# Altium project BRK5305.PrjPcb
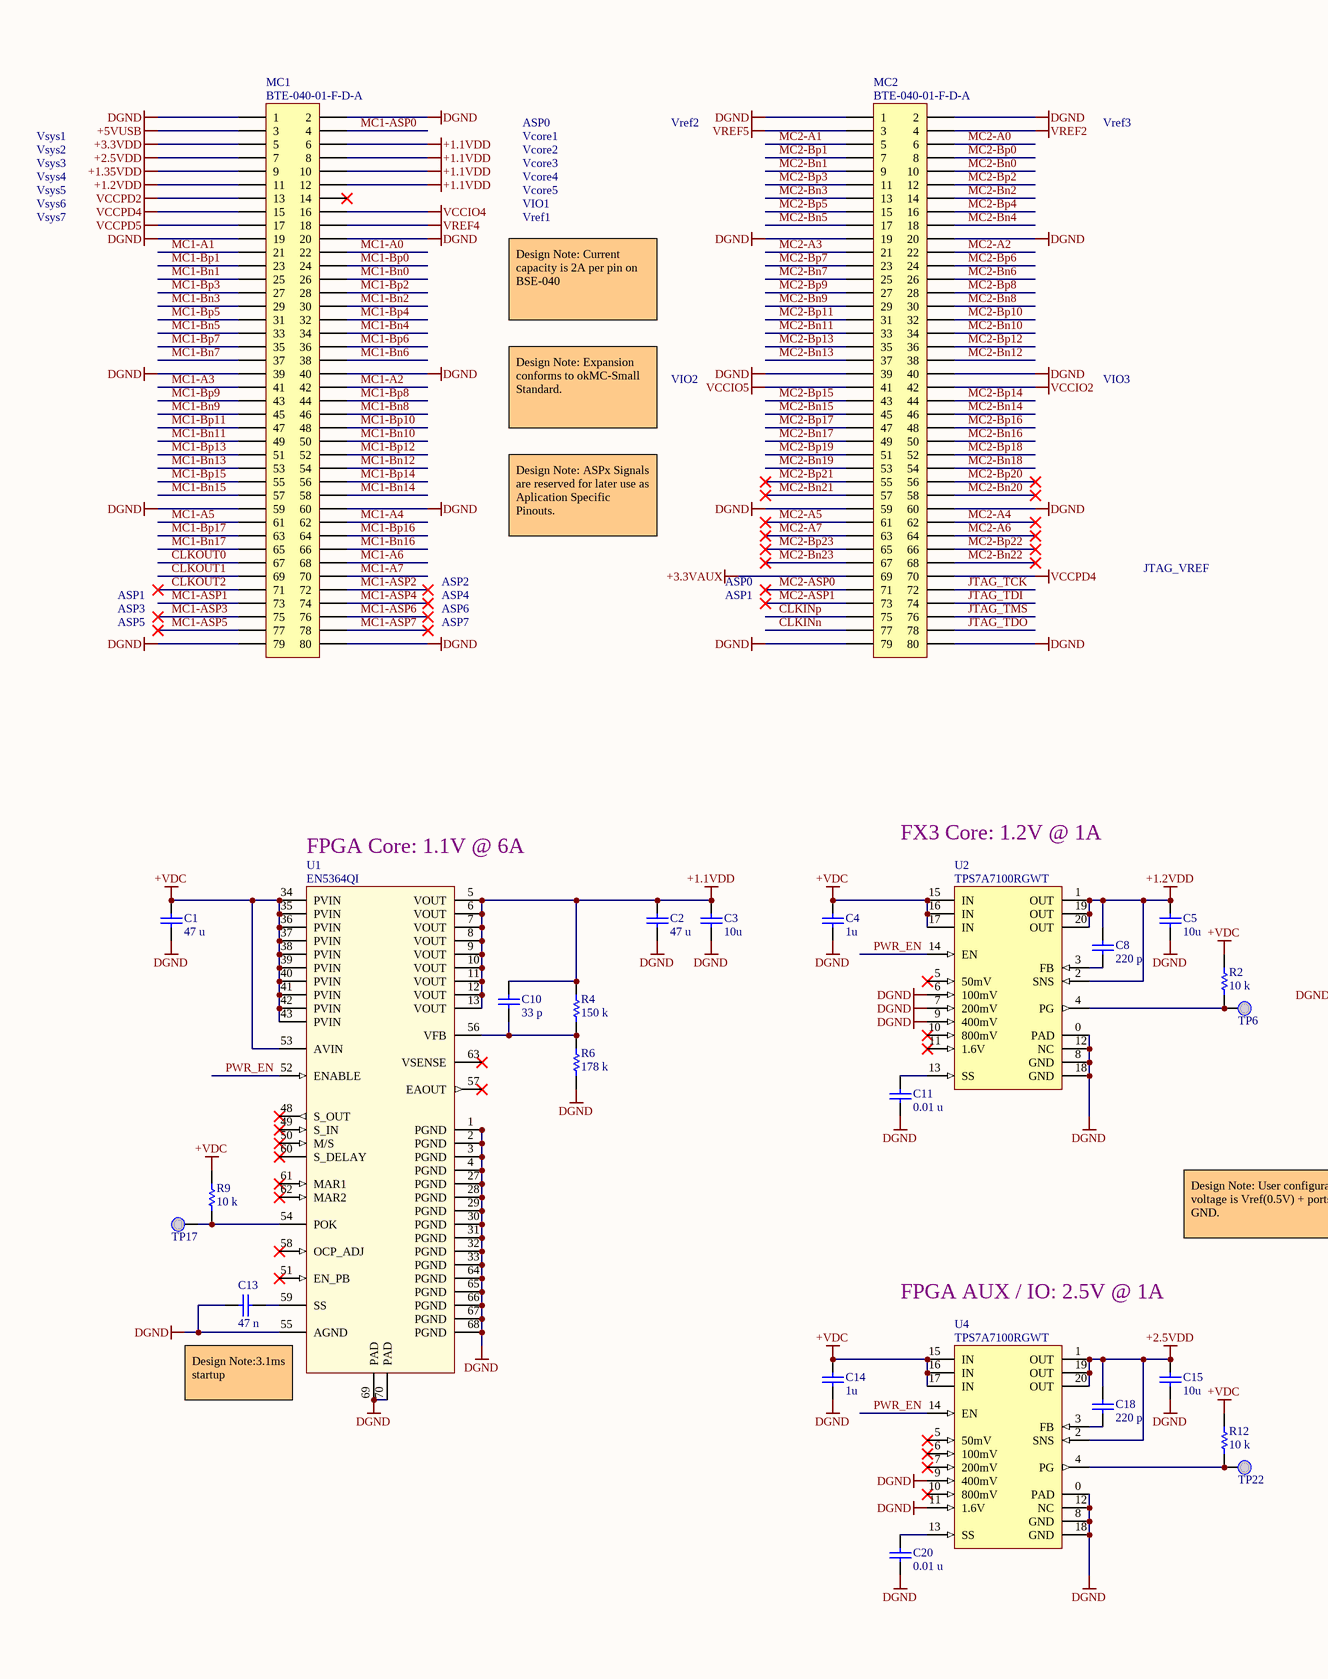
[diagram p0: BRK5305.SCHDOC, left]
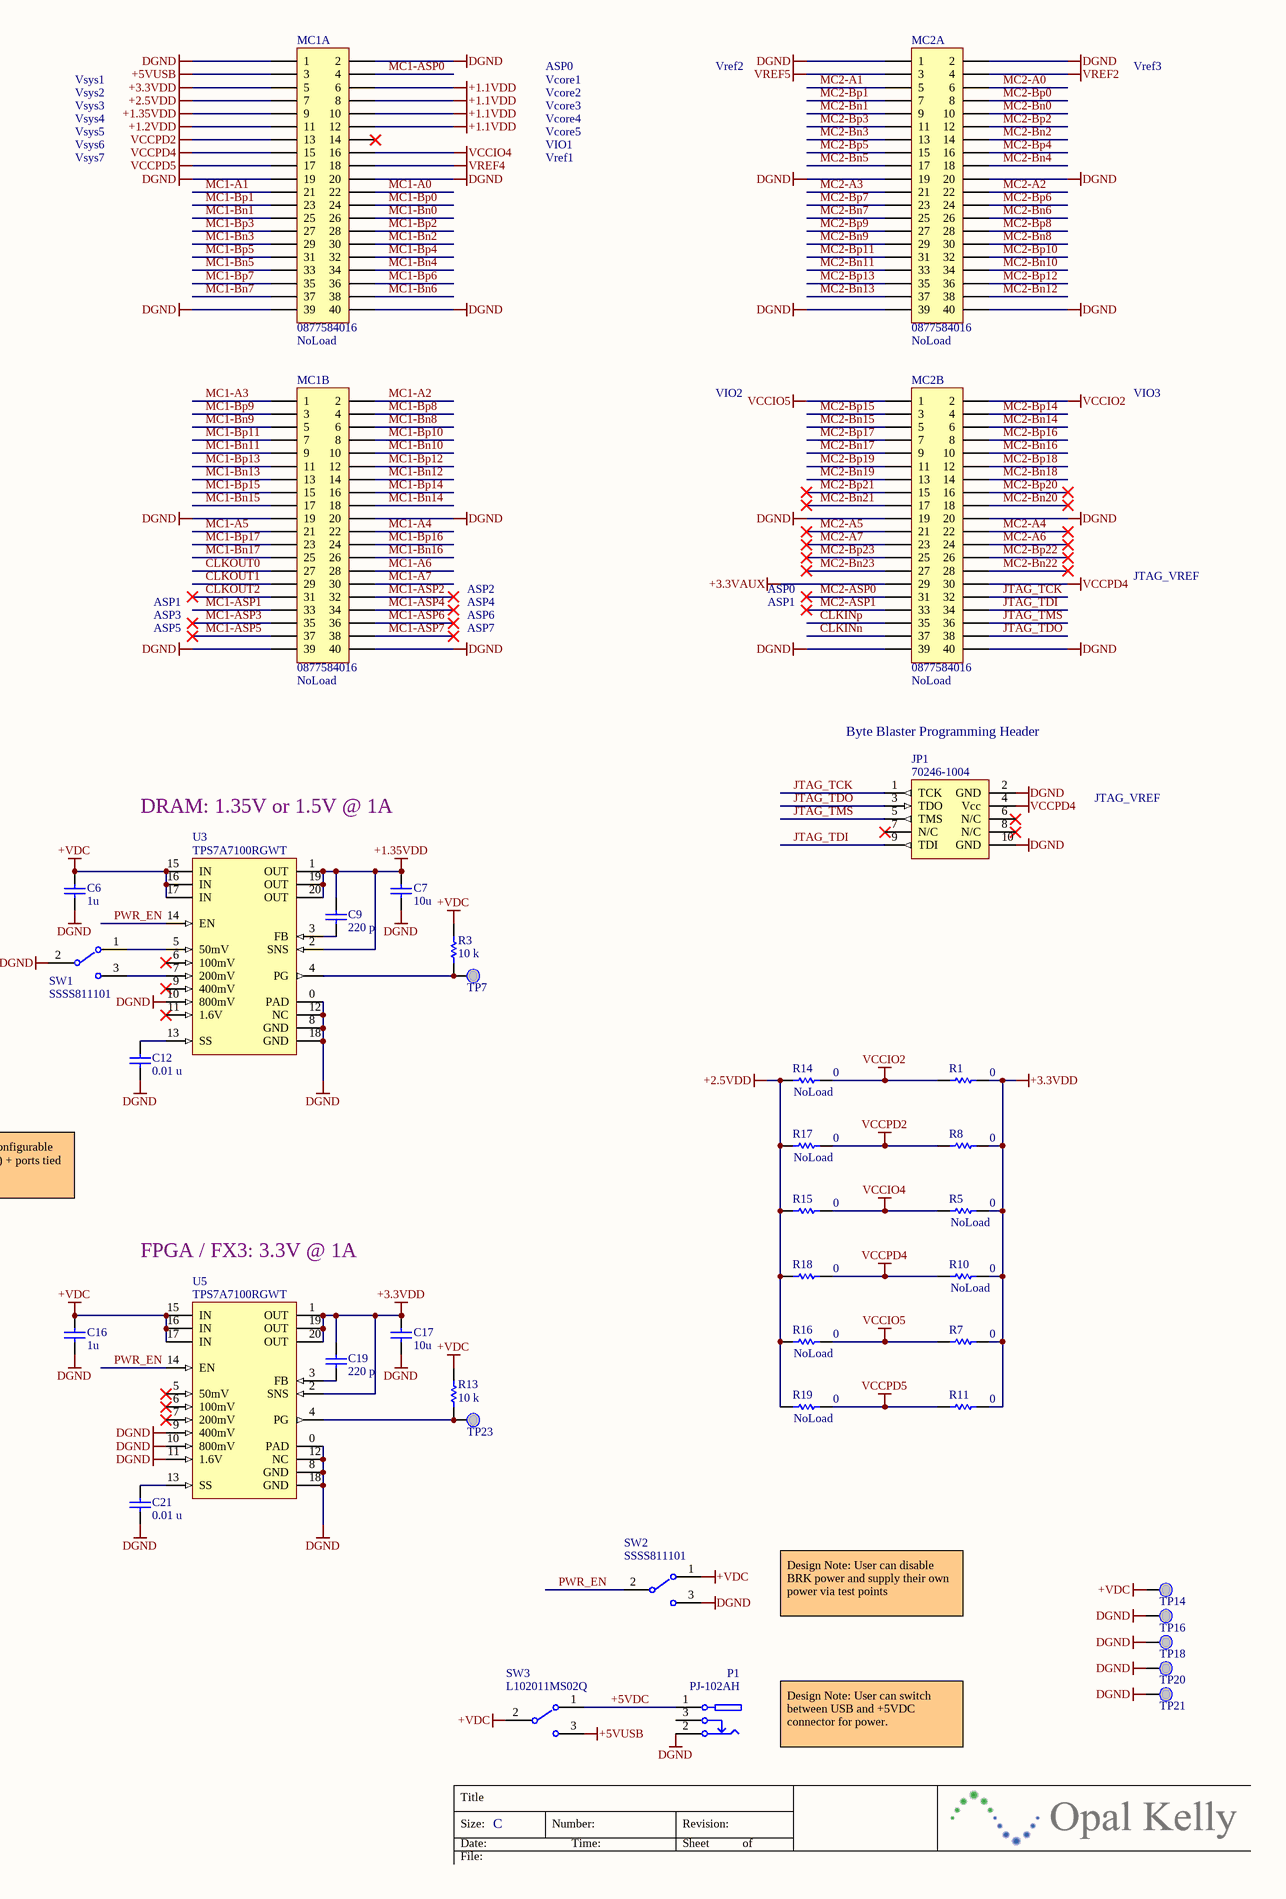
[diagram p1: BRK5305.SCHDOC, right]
1 sheet, 66 parts. Net scope: global (net labels, ports and power ports of the same name join across sheets).
Board file: BRK5305.PcbDoc

## Sheet BRK5305.SCHDOC: BRK5305 BreakOut Board
size C; Author: Casey Smith; Organization: Opal Kelly; Address1: 13500 SW 72nd Ave, STE 100; Address2: Portland, OR 97223; Address3: 217.391.3724; Address4: http://www.opalkelly.com; DocumentNumber: xxx; Revision: 1; SheetNumber: 1; SheetTotal: 1

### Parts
C1  value 47 u  [CAPC3216N]  (hidden comment: JMK316BJ476ML-T)
C2  value 47 u  [CAPC3216N]  (hidden comment: JMK316BJ476ML-T)
C3  value 10u  [CAPC2012N]  (hidden comment: LMK212BJ106KG-T)
C4  value 1u  [CAPC1005N]  (hidden comment: LMK105BJ105KV-F)
C5  value 10u  [CAPC2012N]  (hidden comment: LMK212BJ106KG-T)
C6  value 1u  [CAPC1005N]  (hidden comment: LMK105BJ105KV-F)
C7  value 10u  [CAPC2012N]  (hidden comment: LMK212BJ106KG-T)
C8  value 220 p  [CAPC1005N]  (hidden comment: C0402C221J5GACTU)
C9  value 220 p  [CAPC1005N]  (hidden comment: C0402C221J5GACTU)
C10  value 33 p  [CAPC1005N]  (hidden comment: C0402C330J5GACTU)
C11  value 0.01 u  [CAPC1005N]  (hidden comment: C0402C103K4RACTU)
C12  value 0.01 u  [CAPC1005N]  (hidden comment: C0402C103K4RACTU)
C13  value 47 n  [CAPC1005N]  (hidden comment: EMK105BJ473KV-F)
C14  value 1u  [CAPC1005N]  (hidden comment: LMK105BJ105KV-F)
C15  value 10u  [CAPC2012N]  (hidden comment: LMK212BJ106KG-T)
C16  value 1u  [CAPC1005N]  (hidden comment: LMK105BJ105KV-F)
C17  value 10u  [CAPC2012N]  (hidden comment: LMK212BJ106KG-T)
C18  value 220 p  [CAPC1005N]  (hidden comment: C0402C221J5GACTU)
C19  value 220 p  [CAPC1005N]  (hidden comment: C0402C221J5GACTU)
C20  value 0.01 u  [CAPC1005N]  (hidden comment: C0402C103K4RACTU)
C21  value 0.01 u  [CAPC1005N]  (hidden comment: C0402C103K4RACTU)
JP1  70246-1004  [HDR2X5-SHRD]
MC1  BTE-040-01-F-D-A  [BTE-040]
MC1A  0877584016  [HDR2X20-2MM]
MC1B  0877584016  [HDR2X20-2MM]
MC2  BTE-040-01-F-D-A  [BTE-040]
MC2A  0877584016  [HDR2X20-2MM]
MC2B  0877584016  [HDR2X20-2MM]
P1  PJ-102AH  [CUI-PJ102A]
R1  value 0  [RESC1005N]  (hidden comment: CRCW04020000Z0ED)
R2  value 10 k  [RESC1005N]  (hidden comment: CRCW040210K0JNED)
R3  value 10 k  [RESC1005N]  (hidden comment: CRCW040210K0JNED)
R4  value 150 k  [RESC1005N]  (hidden comment: CRCW0402150KFKED)
R5  value 0  [RESC1005N]  (hidden comment: CRCW04020000Z0ED)
R6  value 178 k  [RESC1005N]  (hidden comment: CRCW0402178KFKED)
R7  value 0  [RESC1005N]  (hidden comment: CRCW04020000Z0ED)
R8  value 0  [RESC1005N]  (hidden comment: CRCW04020000Z0ED)
R9  value 10 k  [RESC1005N]  (hidden comment: CRCW040210K0JNED)
R10  value 0  [RESC1005N]  (hidden comment: CRCW04020000Z0ED)
R11  value 0  [RESC1005N]  (hidden comment: CRCW04020000Z0ED)
R12  value 10 k  [RESC1005N]  (hidden comment: CRCW040210K0JNED)
R13  value 10 k  [RESC1005N]  (hidden comment: CRCW040210K0JNED)
R14  value 0  [RESC1005N]  (hidden comment: CRCW04020000Z0ED)
R15  value 0  [RESC1005N]  (hidden comment: CRCW04020000Z0ED)
R16  value 0  [RESC1005N]  (hidden comment: CRCW04020000Z0ED)
R17  value 0  [RESC1005N]  (hidden comment: CRCW04020000Z0ED)
R18  value 0  [RESC1005N]  (hidden comment: CRCW04020000Z0ED)
R19  value 0  [RESC1005N]  (hidden comment: CRCW04020000Z0ED)
SW1  SSSS811101  [SSSS811101]
SW2  SSSS811101  [SSSS811101]
SW3  L102011MS02Q  [L102011MS]
TP6  1.2V POK  [TP_SMALL]  (value not drawn)
TP7  1.35V/1.5V POK  [TP_SMALL]  (value not drawn)
TP14  +VDC  [TP_MED]  (value not drawn)
TP16  GND  [TP_MED]  (value not drawn)
TP17  1.1V POK  [TP_SMALL]  (value not drawn)
TP18  GND  [TP_MED]  (value not drawn)
TP20  GND  [TP_MED]  (value not drawn)
TP21  GND  [TP_MED]  (value not drawn)
TP22  2.5V POK  [TP_SMALL]  (value not drawn)
TP23  3.3V POK  [TP_SMALL]  (value not drawn)
U1  EN5364QI  [EN5364]
U2  TPS7A7100RGWT  [S-PVQN-N20]
U3  TPS7A7100RGWT  [S-PVQN-N20]
U4  TPS7A7100RGWT  [S-PVQN-N20]
U5  TPS7A7100RGWT  [S-PVQN-N20]

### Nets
+1.1VDD: C2.2 C3.2 C10.2 MC1.6 MC1.8 MC1.10 MC1.12 MC1A.6 MC1A.8 MC1A.10 MC1A.12 R4.2 U1.5(VOUT) U1.6(VOUT) U1.7(VOUT) U1.8(VOUT) U1.9(VOUT) U1.10(VOUT) U1.11(VOUT) U1.12(VOUT) U1.13(VOUT)
+1.2VDD: C5.2 C8.2 MC1.11 MC1A.11 U2.1(OUT) U2.2(SNS) U2.19(OUT) U2.20(OUT)
+1.35VDD: C7.2 C9.2 MC1.9 MC1A.9 U3.1(OUT) U3.2(SNS) U3.19(OUT) U3.20(OUT)
+2.5VDD: C15.2 C18.2 MC1.7 MC1A.7 R14.1 R15.1 R16.1 R17.1 R18.1 R19.1 U4.1(OUT) U4.2(SNS) U4.19(OUT) U4.20(OUT)
+3.3VAUX: MC2.69 MC2B.29
+3.3VDD: C17.2 C19.2 MC1.5 MC1A.5 R1.2 R5.2 R7.2 R8.2 R10.2 R11.2 U5.1(OUT) U5.2(SNS) U5.19(OUT) U5.20(OUT)
+5VUSB: MC1.3 MC1A.3 SW3.3
+VDC: C1.2 C4.2 C6.2 C14.2 C16.2 R2.2 R3.2 R9.2 R12.2 R13.2 SW2.1 SW3.2 TP14.1(PIN) U1.34(PVIN) U1.35(PVIN) U1.36(PVIN) U1.37(PVIN) U1.38(PVIN) U1.39(PVIN) U1.40(PVIN) U1.41(PVIN) U1.42(PVIN) U1.43(PVIN) U1.53(AVIN) U2.15(IN) U2.16(IN) U2.17(IN) U3.15(IN) U3.16(IN) U3.17(IN) U4.15(IN) U4.16(IN) U4.17(IN) U5.15(IN) U5.16(IN) U5.17(IN)
DGND: C1.1 C2.1 C3.1 C4.1 C5.1 C6.1 C7.1 C11.1 C12.1 C13.1 C14.1 C15.1 C16.1 C17.1 C20.1 C21.1 JP1.2(GND) JP1.10(GND) MC1.1 MC1.2 MC1.19 MC1.20 MC1.39 MC1.40 MC1.59 MC1.60 MC1.79 MC1.80 MC1A.1 MC1A.2 MC1A.19 MC1A.20 MC1A.39 MC1A.40 MC1B.19 MC1B.20 MC1B.39 MC1B.40 MC2.1 MC2.2 MC2.19 MC2.20 MC2.39 MC2.40 MC2.59 MC2.60 MC2.79 MC2.80 MC2A.1 MC2A.2 MC2A.19 MC2A.20 MC2A.39 MC2A.40 MC2B.19 MC2B.20 MC2B.39 MC2B.40 P1.2 R6.1 SW1.2 SW2.3 TP16.1(PIN) TP18.1(PIN) TP20.1(PIN) TP21.1(PIN) U1.1(PGND) U1.2(PGND) U1.3(PGND) U1.4(PGND) U1.27(PGND) U1.28(PGND) U1.29(PGND) U1.30(PGND) U1.31(PGND) U1.32(PGND) U1.33(PGND) U1.55(AGND) U1.64(PGND) U1.65(PGND) U1.66(PGND) U1.67(PGND) U1.68(PGND) U1.69(PAD) U1.70(PAD) U2.0(PAD) U2.6(100mV) U2.7(200mV) U2.8(GND) U2.9(400mV) U2.12(NC) U2.18(GND) U3.0(PAD) U3.8(GND) U3.10(800mV) U3.12(NC) U3.18(GND) U4.0(PAD) U4.8(GND) U4.9(400mV) U4.11(1.6V) U4.12(NC) U4.18(GND) U5.0(PAD) U5.8(GND) U5.9(400mV) U5.10(800mV) U5.11(1.6V) U5.12(NC) U5.18(GND)
VCCIO2: MC2.42 MC2B.2 R1.1 R14.2
VCCIO4: MC1.16 MC1A.16 R5.1 R15.2
VCCIO5: MC2.41 MC2B.1 R7.1 R16.2
VCCPD2: MC1.13 MC1A.13 R8.1 R17.2
VCCPD4: JP1.4(Vcc) MC1.15 MC1A.15 MC2.70 MC2B.30 R10.1 R18.2
VCCPD5: MC1.17 MC1A.17 R11.1 R19.2
VREF2: MC2.4 MC2A.4
VREF4: MC1.18 MC1A.18
VREF5: MC2.3 MC2A.3
+5VDC: P1.1 SW3.1
CLKINn: MC2.77 MC2B.37
CLKINp: MC2.75 MC2B.35
CLKOUT0: MC1.67 MC1B.27
CLKOUT1: MC1.69 MC1B.29
CLKOUT2: MC1.71 MC1B.31
JTAG_TCK: JP1.1(TCK) MC2.72 MC2B.32
JTAG_TDI: JP1.9(TDI) MC2.74 MC2B.34
JTAG_TDO: JP1.3(TDO) MC2.78 MC2B.38
JTAG_TMS: JP1.5(TMS) MC2.76 MC2B.36
MC1-A0: MC1.22 MC1A.22
MC1-A1: MC1.21 MC1A.21
MC1-A2: MC1.42 MC1B.2
MC1-A3: MC1.41 MC1B.1
MC1-A4: MC1.62 MC1B.22
MC1-A5: MC1.61 MC1B.21
MC1-A6: MC1.68 MC1B.28
MC1-A7: MC1.70 MC1B.30
MC1-ASP0: MC1.4 MC1A.4
MC1-ASP1: MC1.73 MC1B.33
MC1-ASP2: MC1.72 MC1B.32
MC1-ASP3: MC1.75 MC1B.35
MC1-ASP4: MC1.74 MC1B.34
MC1-ASP5: MC1.77 MC1B.37
MC1-ASP6: MC1.76 MC1B.36
MC1-ASP7: MC1.78 MC1B.38
MC1-Bn0: MC1.26 MC1A.26
MC1-Bn1: MC1.25 MC1A.25
MC1-Bn2: MC1.30 MC1A.30
MC1-Bn3: MC1.29 MC1A.29
MC1-Bn4: MC1.34 MC1A.34
MC1-Bn5: MC1.33 MC1A.33
MC1-Bn6: MC1.38 MC1A.38
MC1-Bn7: MC1.37 MC1A.37
MC1-Bn8: MC1.46 MC1B.6
MC1-Bn9: MC1.45 MC1B.5
MC1-Bn10: MC1.50 MC1B.10
MC1-Bn11: MC1.49 MC1B.9
MC1-Bn12: MC1.54 MC1B.14
MC1-Bn13: MC1.53 MC1B.13
MC1-Bn14: MC1.58 MC1B.18
MC1-Bn15: MC1.57 MC1B.17
MC1-Bn16: MC1.66 MC1B.26
MC1-Bn17: MC1.65 MC1B.25
MC1-Bp0: MC1.24 MC1A.24
MC1-Bp1: MC1.23 MC1A.23
MC1-Bp2: MC1.28 MC1A.28
MC1-Bp3: MC1.27 MC1A.27
MC1-Bp4: MC1.32 MC1A.32
MC1-Bp5: MC1.31 MC1A.31
MC1-Bp6: MC1.36 MC1A.36
MC1-Bp7: MC1.35 MC1A.35
MC1-Bp8: MC1.44 MC1B.4
MC1-Bp9: MC1.43 MC1B.3
MC1-Bp10: MC1.48 MC1B.8
MC1-Bp11: MC1.47 MC1B.7
MC1-Bp12: MC1.52 MC1B.12
MC1-Bp13: MC1.51 MC1B.11
MC1-Bp14: MC1.56 MC1B.16
MC1-Bp15: MC1.55 MC1B.15
MC1-Bp16: MC1.64 MC1B.24
MC1-Bp17: MC1.63 MC1B.23
MC2-A0: MC2.6 MC2A.6
MC2-A1: MC2.5 MC2A.5
MC2-A2: MC2.22 MC2A.22
MC2-A3: MC2.21 MC2A.21
MC2-A4: MC2.62 MC2B.22
MC2-A5: MC2.61 MC2B.21
MC2-A6: MC2.64 MC2B.24
MC2-A7: MC2.63 MC2B.23
MC2-ASP0: MC2.71 MC2B.31
MC2-ASP1: MC2.73 MC2B.33
MC2-Bn0: MC2.10 MC2A.10
MC2-Bn1: MC2.9 MC2A.9
MC2-Bn2: MC2.14 MC2A.14
MC2-Bn3: MC2.13 MC2A.13
MC2-Bn4: MC2.18 MC2A.18
MC2-Bn5: MC2.17 MC2A.17
MC2-Bn6: MC2.26 MC2A.26
MC2-Bn7: MC2.25 MC2A.25
MC2-Bn8: MC2.30 MC2A.30
MC2-Bn9: MC2.29 MC2A.29
MC2-Bn10: MC2.34 MC2A.34
MC2-Bn11: MC2.33 MC2A.33
MC2-Bn12: MC2.38 MC2A.38
MC2-Bn13: MC2.37 MC2A.37
MC2-Bn14: MC2.46 MC2B.6
MC2-Bn15: MC2.45 MC2B.5
MC2-Bn16: MC2.50 MC2B.10
MC2-Bn17: MC2.49 MC2B.9
MC2-Bn18: MC2.54 MC2B.14
MC2-Bn19: MC2.53 MC2B.13
MC2-Bn20: MC2.58 MC2B.18
MC2-Bn21: MC2.57 MC2B.17
MC2-Bn22: MC2.68 MC2B.28
MC2-Bn23: MC2.67 MC2B.27
MC2-Bp0: MC2.8 MC2A.8
MC2-Bp1: MC2.7 MC2A.7
MC2-Bp2: MC2.12 MC2A.12
MC2-Bp3: MC2.11 MC2A.11
MC2-Bp4: MC2.16 MC2A.16
MC2-Bp5: MC2.15 MC2A.15
MC2-Bp6: MC2.24 MC2A.24
MC2-Bp7: MC2.23 MC2A.23
MC2-Bp8: MC2.28 MC2A.28
MC2-Bp9: MC2.27 MC2A.27
MC2-Bp10: MC2.32 MC2A.32
MC2-Bp11: MC2.31 MC2A.31
MC2-Bp12: MC2.36 MC2A.36
MC2-Bp13: MC2.35 MC2A.35
MC2-Bp14: MC2.44 MC2B.4
MC2-Bp15: MC2.43 MC2B.3
MC2-Bp16: MC2.48 MC2B.8
MC2-Bp17: MC2.47 MC2B.7
MC2-Bp18: MC2.52 MC2B.12
MC2-Bp19: MC2.51 MC2B.11
MC2-Bp20: MC2.56 MC2B.16
MC2-Bp21: MC2.55 MC2B.15
MC2-Bp22: MC2.66 MC2B.26
MC2-Bp23: MC2.65 MC2B.25
PWR_EN: SW2.2 U1.52(ENABLE) U2.14(EN) U3.14(EN) U4.14(EN) U5.14(EN)
NetC8_1: C8.1 U2.3(FB)
NetC9_1: C9.1 U3.3(FB)
NetC10_1: C10.1 R4.1 R6.2 U1.56(VFB)
NetC11_2: C11.2 U2.13(SS)
NetC12_2: C12.2 U3.13(SS)
NetC13_2: C13.2 U1.59(SS)
NetC18_1: C18.1 U4.3(FB)
NetC19_1: C19.1 U5.3(FB)
NetC20_2: C20.2 U4.13(SS)
NetC21_2: C21.2 U5.13(SS)
NetR2_1: R2.1 TP6.1(PIN) U2.4(PG)
NetR3_1: R3.1 TP7.1(PIN) U3.4(PG)
NetR9_1: R9.1 TP17.1(PIN) U1.54(POK)
NetR12_1: R12.1 TP22.1(PIN) U4.4(PG)
NetR13_1: R13.1 TP23.1(PIN) U5.4(PG)
NetSW1_1: SW1.1 U3.5(50mV)
NetSW1_3: SW1.3 U3.7(200mV)

Not connected (* = marked no-connect by the designer): JP1 6(N/C)* 7(N/C)* 8(N/C)*; MC1 14*; MC1A 14*; P1 3; U1 48(S_OUT)* 49(S_IN)* 50(M/S)* 51(EN_PB)* 57(EAOUT)* 58(OCP_ADJ)* 60(S_DELAY)* 61(MAR1)* 62(MAR2)* 63(VSENSE)*; U2 5(50mV)* 10(800mV)* 11(1.6V)*; U3 6(100mV)* 9(400mV)* 11(1.6V)*; U4 5(50mV)* 6(100mV)* 7(200mV)* 10(800mV)*; U5 5(50mV)* 6(100mV)* 7(200mV)*

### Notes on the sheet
- Vsys1
- Vsys2
- ASP0
- Vcore2
- Vcore1
- Vref2
- Vref3
- Vsys3
- Vcore3
- Vsys4
- Vsys5
- Vsys6
- Vsys7
- Vcore4
- VIO1
- Vref1
- Vcore5
- Design Note: Current capacity is 2A per pin on BSE-040
- Design Note: Expansion conforms to okMC-Small Standard.
- VIO2
- VIO3
- Design Note: ASPx Signals are reserved for later use as Aplication Specific Pinouts.
- JTAG_VREF
- ASP1
- ASP3
- ASP5
- ASP7
- ASP2
- ASP4
- ASP6
- Byte Blaster Programming Header
- FX3 Core: 1.2V @ 1A
- DRAM: 1.35V or 1.5V @ 1A
- (near U1) FPGA Core: 1.1V @ 6A
- Design Note: User configurable voltage is Vref(0.5V) + ports tied to GND.
- FPGA AUX / IO: 2.5V @ 1A
- FPGA / FX3: 3.3V @ 1A
- (near U1) Design Note:3.1ms startup
- Design Note: User can disable BRK power and supply their own power via test points
- Title
- Design Note: User can switch between USB and +5VDC connector for power.
- Size:
- Date:
- File:
- C
- Number:
- Time:
- Revision:
- Sheet
- of

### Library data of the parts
C1 C2 = 000570: Ceramic Capacitor; Manufacturer: Taiyo Yuden; partnumber: 000570; Description 2: 1206, 6.3V; ValueFloat: 4.7E-5; Tolerance (%): 20
C3 C5 C7 C15 C17 = 000491: Ceramic capacitor; Manufacturer: Taiyo Yuden; partnumber: 000491; Description 2: SM-0805, 10%, 10v; ValueFloat: 1E-5; Tolerance (%): 10
C4 C6 C14 C16 = 000480: Ceramic capacitor; Manufacturer: Taiyo Yuden; partnumber: 000480; Description 2: SM-0402, 10%, 10v; ValueFloat: 1E-6; Tolerance (%): 10
C8 C9 C18 C19 = 001219: Ceramic capacitor; Manufacturer: Kemet; partnumber: 001219; Description 2: SM-0402, 5%, 50v; ValueFloat: 2.2E-10; Tolerance (%): 5
C10 = 000935: Ceramic capacitor; Manufacturer: Kemet; partnumber: 000935; Description 2: SM-0402, 5%, 50v; ValueFloat: 3.3E-11; Tolerance (%): 5
C11 C12 C20 C21 = 000295: Ceramic Capacitor; Manufacturer: Kemet; partnumber: 000295; Description 2: SM-0402, 10%, 6.3V, X5R; ValueFloat: 1E-8; Tolerance (%): 10
C13 = 000335: Ceramic Capacitor; Manufacturer: Taiyo Yuden; partnumber: 000335; Description 2: SM-0402, 10%, 16V, X7R; ValueFloat: 4.7E-8; Tolerance (%): 10
JP1 = 000777: 2.54mm, 10 Pos, Dual Row Header; Manufacturer: Molex; partnumber: 000777; Description 2: Altera JTAG Compatible
MC1 MC2 = 000059: 0.8mm high-density header; Manufacturer: Samtec; partnumber: 000059; Description 2: 80-pin, Gold flash, Mated height: 5.00mm (0.197 inch)
MC1A MC1B MC2A MC2B = 000583: 2mm header, 20x2, thru-hole; Manufacturer: Molex; partnumber: 000583
P1 = 000356: DC power connector - high current; Manufacturer: CUI Inc.; partnumber: 000356; Description 2: 2.1mm / 5.5mm
R1 R5 R7 R8 R10 R11 R14-R19 = 000755: Thick-film resistor; Manufacturer: Vishay; partnumber: 000755; Description 2: SM-0402, 1%, 1/16W; Tolerance (%): 1
R2 R3 R9 R12 R13 = 000759: Thick-film resistor; Manufacturer: Vishay; partnumber: 000759; Description 2: SM-0402, 5%, 1/16W; ValueFloat: 10000; Tolerance (%): 5
R4 = 000796: Thick-film resistor; Manufacturer: Vishay; partnumber: 000796; Description 2: SM-0402, 1%, 1/16W; ValueFloat: 150000; Tolerance (%): 1
R6 = 001310: Thick-film resistor; Manufacturer: Vishay; partnumber: 001310; Description 2: SM-0402, 1%, 1/16W; ValueFloat: 178000; Tolerance (%): 1
SW1 SW2 = 000231: Slide; Manufacturer: Alps; partnumber: 000231; Description 2: 1 position, 2 pole, SMT slide switch
SW3 = 001220: SPDT; Manufacturer: C&K Components; partnumber: 001220; Description 2: PC Thru-Hole Mount, PC Thru-Hole Termination
TP6 TP7 TP14 TP16-TP18 TP20-TP23 = 000812: Testpoint.; Manufacturer: Opal Kelly Incorporated; Manufacturer_PN: PCB-TESTPOINT; partnumber: 000812
U1 = 000576: 6A Synchronous Buck DC-DC converter; Manufacturer: Altera; partnumber: 000576; Description 2: 2.375v - 6.6v input, 4MHz switching
U2-U5 = 001209: LDO voltage regulator; Manufacturer: Texas Instruments; partnumber: 001209; Description 2: Vin: 1.5V-6.5V Vout Fixed: 0.9V-3.5V Vout Adj:0,9V-5V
